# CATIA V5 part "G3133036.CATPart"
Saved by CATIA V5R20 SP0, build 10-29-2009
Part number: G3133036
Revision: 8
Definition: design
Nomenclature: G3133036
Source: made
Description: NOT SPECIFIED
Bounding box of the stored display mesh (mm): x -27 to 36, y -23.329 to 23.329, z -23.5 to 23.5
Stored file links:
  C:\Users\Raffaele\Desktop\3D X SITO CF\BOLEX\24-BUSH REF 313\G3133036.CATPart
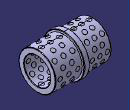
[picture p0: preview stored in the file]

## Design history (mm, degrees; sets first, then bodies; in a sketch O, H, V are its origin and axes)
Body1 "MANIFOLD_SOLID_BREP #11913" (main body)
  Solid1: solid without history
Body2 "MANIFOLD_SOLID_BREP #12068"
  Solid2: solid without history
Body3 "MANIFOLD_SOLID_BREP #12223"
  Solid3: solid without history
Body4 "MANIFOLD_SOLID_BREP #12376"
  Solid4: solid without history
Body5 "MANIFOLD_SOLID_BREP #12533"
  Solid5: solid without history
Body6 "MANIFOLD_SOLID_BREP #12686"
  Solid6: solid without history
Body7 "MANIFOLD_SOLID_BREP #12839"
  Solid7: solid without history
Body8 "MANIFOLD_SOLID_BREP #12996"
  Solid8: solid without history
Body9 "MANIFOLD_SOLID_BREP #13149"
  Solid9: solid without history
Body10 "MANIFOLD_SOLID_BREP #13306"
  Solid10: solid without history
Body11 "MANIFOLD_SOLID_BREP #13463"
  Solid11: solid without history
Body12 "MANIFOLD_SOLID_BREP #13620"
  Solid12: solid without history
Body13 "MANIFOLD_SOLID_BREP #13777"
  Solid13: solid without history
Body14 "MANIFOLD_SOLID_BREP #13934"
  Solid14: solid without history
Body15 "MANIFOLD_SOLID_BREP #14091"
  Solid15: solid without history
Body16 "MANIFOLD_SOLID_BREP #14248"
  Solid16: solid without history
Body17 "MANIFOLD_SOLID_BREP #14405"
  Solid17: solid without history
Body18 "MANIFOLD_SOLID_BREP #14558"
  Solid18: solid without history
Body19 "MANIFOLD_SOLID_BREP #14715"
  Solid19: solid without history
Body20 "MANIFOLD_SOLID_BREP #14868"
  Solid20: solid without history
Body21 "MANIFOLD_SOLID_BREP #15021"
  Solid21: solid without history
Body22 "MANIFOLD_SOLID_BREP #15178"
  Solid22: solid without history
Body23 "MANIFOLD_SOLID_BREP #15331"
  Solid23: solid without history
Body24 "MANIFOLD_SOLID_BREP #15486"
  Solid24: solid without history
Body25 "MANIFOLD_SOLID_BREP #15641"
  Solid25: solid without history
Body26 "MANIFOLD_SOLID_BREP #15794"
  Solid26: solid without history
Body27 "MANIFOLD_SOLID_BREP #15951"
  Solid27: solid without history
Body28 "MANIFOLD_SOLID_BREP #16104"
  Solid28: solid without history
Body29 "MANIFOLD_SOLID_BREP #16257"
  Solid29: solid without history
Body30 "MANIFOLD_SOLID_BREP #16414"
  Solid30: solid without history
Body31 "MANIFOLD_SOLID_BREP #16567"
  Solid31: solid without history
Body32 "MANIFOLD_SOLID_BREP #16722"
  Solid32: solid without history
Body33 "MANIFOLD_SOLID_BREP #16877"
  Solid33: solid without history
Body34 "MANIFOLD_SOLID_BREP #17034"
  Solid34: solid without history
Body35 "MANIFOLD_SOLID_BREP #17191"
  Solid35: solid without history
Body36 "MANIFOLD_SOLID_BREP #17348"
  Solid36: solid without history
Body37 "MANIFOLD_SOLID_BREP #17505"
  Solid37: solid without history
Body38 "MANIFOLD_SOLID_BREP #17662"
  Solid38: solid without history
Body39 "MANIFOLD_SOLID_BREP #17819"
  Solid39: solid without history
Body40 "MANIFOLD_SOLID_BREP #17976"
  Solid40: solid without history
Body41 "MANIFOLD_SOLID_BREP #18133"
  Solid41: solid without history
Body42 "MANIFOLD_SOLID_BREP #18286"
  Solid42: solid without history
Body43 "MANIFOLD_SOLID_BREP #18439"
  Solid43: solid without history
Body44 "MANIFOLD_SOLID_BREP #18592"
  Solid44: solid without history
Body45 "MANIFOLD_SOLID_BREP #18749"
  Solid45: solid without history
Body46 "MANIFOLD_SOLID_BREP #18906"
  Solid46: solid without history
Body47 "MANIFOLD_SOLID_BREP #19063"
  Solid47: solid without history
Body48 "MANIFOLD_SOLID_BREP #19216"
  Solid48: solid without history
Body49 "MANIFOLD_SOLID_BREP #19369"
  Solid49: solid without history
Body50 "MANIFOLD_SOLID_BREP #19522"
  Solid50: solid without history
Body51 "MANIFOLD_SOLID_BREP #19675"
  Solid51: solid without history
Body52 "MANIFOLD_SOLID_BREP #19828"
  Solid52: solid without history
Body53 "MANIFOLD_SOLID_BREP #19981"
  Solid53: solid without history
Body54 "MANIFOLD_SOLID_BREP #20138"
  Solid54: solid without history
Body55 "MANIFOLD_SOLID_BREP #20295"
  Solid55: solid without history
Body56 "MANIFOLD_SOLID_BREP #20452"
  Solid56: solid without history
Body57 "MANIFOLD_SOLID_BREP #20605"
  Solid57: solid without history
Body58 "MANIFOLD_SOLID_BREP #20758"
  Solid58: solid without history
Body59 "MANIFOLD_SOLID_BREP #20911"
  Solid59: solid without history
Body60 "MANIFOLD_SOLID_BREP #21066"
  Solid60: solid without history
Body61 "MANIFOLD_SOLID_BREP #21221"
  Solid61: solid without history
Body62 "MANIFOLD_SOLID_BREP #21376"
  Solid62: solid without history
Body63 "MANIFOLD_SOLID_BREP #21531"
  Solid63: solid without history
Body64 "MANIFOLD_SOLID_BREP #21686"
  Solid64: solid without history
Body65 "MANIFOLD_SOLID_BREP #21841"
  Solid65: solid without history
Body66 "MANIFOLD_SOLID_BREP #21998"
  Solid66: solid without history
Body67 "MANIFOLD_SOLID_BREP #22155"
  Solid67: solid without history
Body68 "MANIFOLD_SOLID_BREP #22312"
  Solid68: solid without history
Body69 "MANIFOLD_SOLID_BREP #22469"
  Solid69: solid without history
Body70 "MANIFOLD_SOLID_BREP #22626"
  Solid70: solid without history
Body71 "MANIFOLD_SOLID_BREP #22783"
  Solid71: solid without history
Body72 "MANIFOLD_SOLID_BREP #22940"
  Solid72: solid without history
Body73 "MANIFOLD_SOLID_BREP #23097"
  Solid73: solid without history
Body74 "MANIFOLD_SOLID_BREP #23254"
  Solid74: solid without history
Body75 "MANIFOLD_SOLID_BREP #23411"
  Solid75: solid without history
Body76 "MANIFOLD_SOLID_BREP #23568"
  Solid76: solid without history
Body77 "MANIFOLD_SOLID_BREP #23725"
  Solid77: solid without history
Body78 "MANIFOLD_SOLID_BREP #23882"
  Solid78: solid without history
Body79 "MANIFOLD_SOLID_BREP #24039"
  Solid79: solid without history
Body80 "MANIFOLD_SOLID_BREP #24196"
  Solid80: solid without history
Body81 "MANIFOLD_SOLID_BREP #24353"
  Solid81: solid without history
